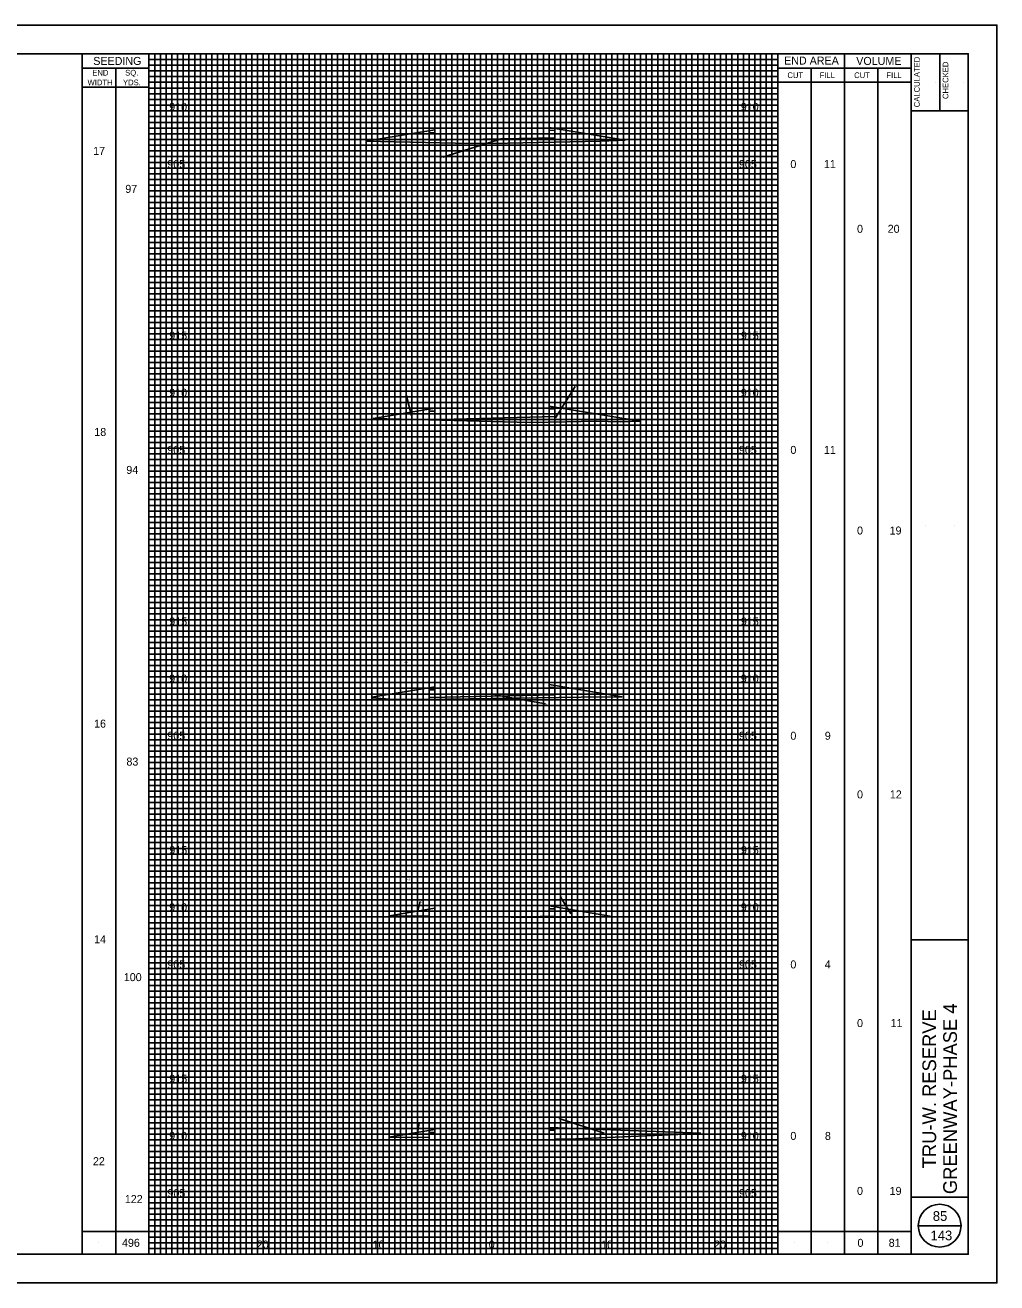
# Model space of a CAD drawing. Extents: x -73 to 160, y -2 to 1877.
# Drawn here: x 75 to 160, y 1262.5 to 1372.5 of the extents above; entities that cross this region are included whole.
import ezdxf

# ---------------------------------------------------------------- set-up
doc = ezdxf.new("R2010")
doc.units = 0
for name, color, linetype in [('DR_P_Flood_Boundary', 7, 'Continuous'), ('GK_Cells', 7, 'Continuous'), ('RD_X_Fence', 7, 'Continuous'), ('TX_X_5', 7, 'Continuous'), ('UT_P_Water_Cells', 7, 'Continuous'), ('XS_P_Pavt_Layers', 7, 'Continuous'), ('XS_P_Pavt_Surface', 7, 'Continuous'), ('XS_X_Ground_Line', 7, 'Continuous')]:
    doc.layers.add(name, color=color, linetype=linetype)

msp = doc.modelspace()

# ---------------------------------------------------------------- linework, layer by layer
at = {"layer": 'DR_P_Flood_Boundary'}
for p, q in [((90.83, 1265), (90.83, 1370)), ((95.83, 1265), (95.83, 1370)), ((100.83, 1265), (100.83, 1370)), ((105.83, 1265), (105.83, 1370)), ((110.83, 1265), (110.83, 1370)), ((115.83, 1265), (115.83, 1370)), ((120.83, 1265), (120.83, 1370)), ((125.83, 1265), (125.83, 1370)), ((130.83, 1265), (130.83, 1370)), ((135.83, 1265), (135.83, 1370)), ((85.83, 1365), (140.83, 1365)), ((85.83, 1360), (140.83, 1360)), ((85.83, 1355), (140.83, 1355)), ((85.83, 1350), (140.83, 1350)), ((85.83, 1345), (140.83, 1345)), ((85.83, 1340), (140.83, 1340)), ((85.83, 1335), (140.83, 1335)), ((85.83, 1330), (140.83, 1330)), ((85.83, 1325), (140.83, 1325)), ((85.83, 1320), (140.83, 1320)), ((85.83, 1315), (140.83, 1315)), ((85.83, 1310), (140.83, 1310)), ((85.83, 1305), (140.83, 1305)), ((85.83, 1300), (140.83, 1300)), ((85.83, 1295), (140.83, 1295)), ((85.83, 1290), (140.83, 1290)), ((85.83, 1285), (140.83, 1285)), ((85.83, 1280), (140.83, 1280)), ((85.83, 1275), (140.83, 1275)), ((85.83, 1270), (140.83, 1270))]:
    msp.add_line(p, q, dxfattribs=at)
at = {"layer": 'GK_Cells'}
for p, q in [((152.5, 1265), (152.5, 1370)), ((155, 1370), (155, 1365)), ((152.5, 1365), (157.5, 1365)), ((152.5, 1292.5), (157.5, 1292.5)), ((152.5, 1270), (157.5, 1270))]:
    msp.add_line(p, q, dxfattribs=at)
msp.add_lwpolyline([(0, 1370), (157.5, 1370), (157.5, 1265), (0, 1265)], close=True, dxfattribs=at)
at = {"layer": 'RD_X_Fence'}
for p, q in [((110.83, 1363.35), (104.77, 1362.34)), ((110.33, 1363.09), (110.83, 1363.1)), ((110.33, 1362.43), (110.33, 1363.09)), ((127.5, 1362.44), (120.83, 1363.55)), ((120.83, 1363.3), (121.33, 1363.31)), ((121.33, 1363.31), (121.33, 1362.65)), ((121.33, 1362.65), (110.33, 1362.43)), ((116.75, 1362.58), (111.55, 1360.94)), ((121.39, 1338.16), (123.11, 1340.91)), ((108.79, 1338.35), (108.35, 1340.06)), ((110.83, 1338.99), (105.45, 1338.09)), ((110.33, 1338.73), (110.83, 1338.74)), ((110.33, 1338.06), (110.33, 1338.73)), ((128.81, 1337.86), (120.83, 1339.19)), ((120.83, 1338.94), (121.33, 1338.95)), ((121.33, 1338.95), (121.33, 1338.28)), ((105.45, 1338.09), (110.33, 1337.97)), ((121.33, 1338.28), (110.33, 1337.97)), ((110.83, 1314.63), (105.32, 1313.71)), ((127.23, 1313.76), (120.83, 1314.83)), ((120.83, 1314.58), (121.33, 1314.59)), ((121.33, 1314.59), (121.33, 1313.92)), ((110.33, 1314.37), (110.83, 1314.38)), ((110.33, 1313.7), (110.33, 1314.37)), ((121.33, 1313.92), (110.33, 1313.7)), ((116.1, 1313.92), (120.53, 1313.15)), ((109.3, 1294.81), (109.56, 1295.85)), ((122.72, 1294.78), (121.87, 1296.2)), ((110.83, 1295.26), (106.86, 1294.6)), ((110.33, 1295), (110.83, 1295.01)), ((110.33, 1294.56), (110.33, 1295)), ((126.5, 1294.52), (120.83, 1295.46)), ((120.83, 1295.21), (121.33, 1295.22)), ((121.33, 1295.22), (121.33, 1294.56)), ((106.86, 1294.6), (110.33, 1294.56)), ((121.33, 1294.56), (117.5, 1294.48)), ((109.29, 1275.45), (109.46, 1276.48)), ((134.1, 1275.6), (120.83, 1276.1)), ((125.64, 1275.58), (121.72, 1276.88)), ((110.83, 1275.9), (106.82, 1275.23)), ((106.82, 1275.23), (110.33, 1275.22)), ((110.33, 1275.64), (110.83, 1275.65)), ((110.33, 1275.22), (110.33, 1275.64)), ((120.83, 1275.85), (121.33, 1275.86)), ((121.33, 1275.86), (121.33, 1275.2))]:
    msp.add_line(p, q, dxfattribs=at)
for points in [[(110.83, 1363.1), (110.83, 1363.25), (110.83, 1363.35)], [(120.83, 1363.55), (120.83, 1363.45), (120.83, 1363.3)], [(104.77, 1362.34), (112.64, 1362.18), (115.83, 1362.15), (125.37, 1362.34), (127.5, 1362.44)], [(110.83, 1338.74), (110.83, 1338.89), (110.83, 1338.99)], [(120.83, 1339.19), (120.83, 1339.09), (120.83, 1338.94)], [(110.33, 1337.97), (110.33, 1338.06)], [(110.33, 1337.97), (115.83, 1337.83), (119.16, 1337.75), (122.33, 1337.81), (124.95, 1337.86), (127.05, 1337.82), (128.81, 1337.86)], [(110.83, 1314.38), (110.83, 1314.52), (110.83, 1314.63)], [(120.83, 1314.83), (120.83, 1314.72), (120.83, 1314.58)], [(105.32, 1313.71), (105.33, 1313.68)], [(105.33, 1313.68), (107.3, 1313.51), (108.76, 1313.51), (109.33, 1313.52), (109.71, 1313.51), (115.83, 1313.6), (123.64, 1313.72), (127.23, 1313.76)], [(110.83, 1295.01), (110.83, 1295.16), (110.83, 1295.26)], [(120.83, 1295.46), (120.83, 1295.36), (120.83, 1295.21)], [(117.5, 1294.48), (120.77, 1294.44), (123.95, 1294.49), (126.5, 1294.52)], [(120.83, 1276.1), (120.83, 1276), (120.83, 1275.85)], [(110.83, 1275.65), (110.83, 1275.8), (110.83, 1275.9)], [(121.33, 1275.1), (122.46, 1275.08), (132.79, 1275.51), (134.1, 1275.6)], [(121.33, 1275.2), (121.33, 1275.1)]]:
    msp.add_lwpolyline(points, dxfattribs=at)
at = {"layer": 'TX_X_5'}
msp.add_lwpolyline([(-10, 1262.5), (160, 1262.5), (160, 1372.5), (-10, 1372.5)], close=True, dxfattribs=at)
at = {"layer": 'UT_P_Water_Cells'}
for p, q in [((85.83, 1369.5), (140.83, 1369.5)), ((86.33, 1265), (86.33, 1370)), ((86.83, 1265), (86.83, 1370)), ((87.33, 1265), (87.33, 1370)), ((87.83, 1265), (87.83, 1370)), ((88.33, 1265), (88.33, 1370)), ((88.83, 1265), (88.83, 1370)), ((89.33, 1265), (89.33, 1370)), ((89.83, 1265), (89.83, 1370)), ((90.33, 1265), (90.33, 1370)), ((91.33, 1265), (91.33, 1370)), ((91.83, 1265), (91.83, 1370)), ((92.33, 1265), (92.33, 1370)), ((92.83, 1265), (92.83, 1370)), ((93.33, 1265), (93.33, 1370)), ((93.83, 1265), (93.83, 1370)), ((94.33, 1265), (94.33, 1370)), ((94.83, 1265), (94.83, 1370)), ((95.33, 1265), (95.33, 1370)), ((96.33, 1265), (96.33, 1370)), ((96.83, 1265), (96.83, 1370)), ((97.33, 1265), (97.33, 1370)), ((97.83, 1265), (97.83, 1370)), ((98.33, 1265), (98.33, 1370)), ((98.83, 1265), (98.83, 1370)), ((99.33, 1265), (99.33, 1370)), ((99.83, 1265), (99.83, 1370)), ((100.33, 1265), (100.33, 1370)), ((101.33, 1265), (101.33, 1370)), ((101.83, 1265), (101.83, 1370)), ((102.33, 1265), (102.33, 1370)), ((102.83, 1265), (102.83, 1370)), ((103.33, 1265), (103.33, 1370)), ((103.83, 1265), (103.83, 1370)), ((104.33, 1265), (104.33, 1370)), ((104.83, 1265), (104.83, 1370)), ((105.33, 1265), (105.33, 1370)), ((106.33, 1265), (106.33, 1370)), ((106.83, 1265), (106.83, 1370)), ((107.33, 1265), (107.33, 1370)), ((107.83, 1265), (107.83, 1370)), ((108.33, 1265), (108.33, 1370)), ((108.83, 1265), (108.83, 1370)), ((109.33, 1265), (109.33, 1370)), ((109.83, 1265), (109.83, 1370)), ((110.33, 1265), (110.33, 1370)), ((111.33, 1265), (111.33, 1370)), ((111.83, 1265), (111.83, 1370)), ((112.33, 1265), (112.33, 1370)), ((112.83, 1265), (112.83, 1370)), ((113.33, 1265), (113.33, 1370)), ((113.83, 1265), (113.83, 1370)), ((114.33, 1265), (114.33, 1370)), ((114.83, 1265), (114.83, 1370)), ((115.33, 1265), (115.33, 1370)), ((116.33, 1265), (116.33, 1370)), ((116.83, 1265), (116.83, 1370)), ((117.33, 1265), (117.33, 1370)), ((117.83, 1265), (117.83, 1370)), ((118.33, 1265), (118.33, 1370)), ((118.83, 1265), (118.83, 1370)), ((119.33, 1265), (119.33, 1370)), ((119.83, 1265), (119.83, 1370)), ((120.33, 1265), (120.33, 1370)), ((121.33, 1265), (121.33, 1370)), ((121.83, 1265), (121.83, 1370)), ((122.33, 1265), (122.33, 1370)), ((122.83, 1265), (122.83, 1370)), ((123.33, 1265), (123.33, 1370)), ((123.83, 1265), (123.83, 1370)), ((124.33, 1265), (124.33, 1370)), ((124.83, 1265), (124.83, 1370)), ((125.33, 1265), (125.33, 1370)), ((126.33, 1265), (126.33, 1370)), ((126.83, 1265), (126.83, 1370)), ((127.33, 1265), (127.33, 1370)), ((127.83, 1265), (127.83, 1370)), ((128.33, 1265), (128.33, 1370)), ((128.83, 1265), (128.83, 1370)), ((129.33, 1265), (129.33, 1370)), ((129.83, 1265), (129.83, 1370)), ((130.33, 1265), (130.33, 1370)), ((131.33, 1265), (131.33, 1370)), ((131.83, 1265), (131.83, 1370)), ((132.33, 1265), (132.33, 1370)), ((132.83, 1265), (132.83, 1370)), ((133.33, 1265), (133.33, 1370)), ((133.83, 1265), (133.83, 1370)), ((134.33, 1265), (134.33, 1370)), ((134.83, 1265), (134.83, 1370)), ((135.33, 1265), (135.33, 1370)), ((136.33, 1265), (136.33, 1370)), ((136.83, 1265), (136.83, 1370)), ((137.33, 1265), (137.33, 1370)), ((137.83, 1265), (137.83, 1370)), ((138.33, 1265), (138.33, 1370)), ((138.83, 1265), (138.83, 1370)), ((139.33, 1265), (139.33, 1370)), ((139.83, 1265), (139.83, 1370)), ((140.33, 1265), (140.33, 1370)), ((85.83, 1369), (140.83, 1369)), ((85.83, 1368.5), (140.83, 1368.5)), ((85.83, 1368), (140.83, 1368)), ((85.83, 1367.5), (140.83, 1367.5)), ((85.83, 1367), (140.83, 1367)), ((85.83, 1366.5), (140.83, 1366.5)), ((85.83, 1366), (140.83, 1366)), ((85.83, 1365.5), (140.83, 1365.5)), ((85.83, 1364.5), (140.83, 1364.5)), ((85.83, 1364), (140.83, 1364)), ((85.83, 1363.5), (140.83, 1363.5)), ((85.83, 1363), (140.83, 1363)), ((85.83, 1362.5), (140.83, 1362.5)), ((85.83, 1362), (140.83, 1362)), ((85.83, 1361.5), (140.83, 1361.5)), ((85.83, 1361), (140.83, 1361)), ((85.83, 1360.5), (140.83, 1360.5)), ((85.83, 1359.5), (140.83, 1359.5)), ((85.83, 1359), (140.83, 1359)), ((85.83, 1358.5), (140.83, 1358.5)), ((85.83, 1358), (140.83, 1358)), ((85.83, 1357.5), (140.83, 1357.5)), ((85.83, 1357), (140.83, 1357)), ((85.83, 1356.5), (140.83, 1356.5)), ((85.83, 1356), (140.83, 1356)), ((85.83, 1355.5), (140.83, 1355.5)), ((85.83, 1354.5), (140.83, 1354.5)), ((85.83, 1354), (140.83, 1354)), ((85.83, 1353.5), (140.83, 1353.5)), ((85.83, 1353), (140.83, 1353)), ((85.83, 1352.5), (140.83, 1352.5)), ((85.83, 1352), (140.83, 1352)), ((85.83, 1351.5), (140.83, 1351.5)), ((85.83, 1351), (140.83, 1351)), ((85.83, 1350.5), (140.83, 1350.5)), ((85.83, 1349.5), (140.83, 1349.5)), ((85.83, 1349), (140.83, 1349)), ((85.83, 1348.5), (140.83, 1348.5)), ((85.83, 1348), (140.83, 1348)), ((85.83, 1347.5), (140.83, 1347.5)), ((85.83, 1347), (140.83, 1347)), ((85.83, 1346.5), (140.83, 1346.5)), ((85.83, 1346), (140.83, 1346)), ((85.83, 1345.5), (140.83, 1345.5)), ((85.83, 1344.5), (140.83, 1344.5)), ((85.83, 1344), (140.83, 1344)), ((85.83, 1343.5), (140.83, 1343.5)), ((85.83, 1343), (140.83, 1343)), ((85.83, 1342.5), (140.83, 1342.5)), ((85.83, 1342), (140.83, 1342)), ((85.83, 1341.5), (140.83, 1341.5)), ((85.83, 1341), (140.83, 1341)), ((85.83, 1340.5), (140.83, 1340.5)), ((85.83, 1339.5), (140.83, 1339.5)), ((85.83, 1339), (140.83, 1339)), ((85.83, 1338.5), (140.83, 1338.5)), ((85.83, 1338), (140.83, 1338)), ((85.83, 1337.5), (140.83, 1337.5)), ((85.83, 1337), (140.83, 1337)), ((85.83, 1336.5), (140.83, 1336.5)), ((85.83, 1336), (140.83, 1336)), ((85.83, 1335.5), (140.83, 1335.5)), ((85.83, 1334.5), (140.83, 1334.5)), ((85.83, 1334), (140.83, 1334)), ((85.83, 1333.5), (140.83, 1333.5)), ((85.83, 1333), (140.83, 1333)), ((85.83, 1332.5), (140.83, 1332.5)), ((85.83, 1332), (140.83, 1332)), ((85.83, 1331.5), (140.83, 1331.5)), ((85.83, 1331), (140.83, 1331)), ((85.83, 1330.5), (140.83, 1330.5)), ((85.83, 1329.5), (140.83, 1329.5)), ((85.83, 1329), (140.83, 1329)), ((85.83, 1328.5), (140.83, 1328.5)), ((85.83, 1328), (140.83, 1328)), ((85.83, 1327.5), (140.83, 1327.5)), ((85.83, 1327), (140.83, 1327)), ((85.83, 1326.5), (140.83, 1326.5)), ((85.83, 1326), (140.83, 1326)), ((85.83, 1325.5), (140.83, 1325.5)), ((85.83, 1324.5), (140.83, 1324.5)), ((85.83, 1324), (140.83, 1324)), ((85.83, 1323.5), (140.83, 1323.5)), ((85.83, 1323), (140.83, 1323)), ((85.83, 1322.5), (140.83, 1322.5)), ((85.83, 1322), (140.83, 1322)), ((85.83, 1321.5), (140.83, 1321.5)), ((85.83, 1321), (140.83, 1321)), ((85.83, 1320.5), (140.83, 1320.5)), ((85.83, 1319.5), (140.83, 1319.5)), ((85.83, 1319), (140.83, 1319)), ((85.83, 1318.5), (140.83, 1318.5)), ((85.83, 1318), (140.83, 1318)), ((85.83, 1317.5), (140.83, 1317.5)), ((85.83, 1317), (140.83, 1317)), ((85.83, 1316.5), (140.83, 1316.5)), ((85.83, 1316), (140.83, 1316)), ((85.83, 1315.5), (140.83, 1315.5)), ((85.83, 1314.5), (140.83, 1314.5)), ((85.83, 1314), (140.83, 1314)), ((85.83, 1313.5), (140.83, 1313.5)), ((85.83, 1313), (140.83, 1313)), ((85.83, 1312.5), (140.83, 1312.5)), ((85.83, 1312), (140.83, 1312)), ((85.83, 1311.5), (140.83, 1311.5)), ((85.83, 1311), (140.83, 1311)), ((85.83, 1310.5), (140.83, 1310.5)), ((85.83, 1309.5), (140.83, 1309.5)), ((85.83, 1309), (140.83, 1309)), ((85.83, 1308.5), (140.83, 1308.5)), ((85.83, 1308), (140.83, 1308)), ((85.83, 1307.5), (140.83, 1307.5)), ((85.83, 1307), (140.83, 1307)), ((85.83, 1306.5), (140.83, 1306.5)), ((85.83, 1306), (140.83, 1306)), ((85.83, 1305.5), (140.83, 1305.5)), ((85.83, 1304.5), (140.83, 1304.5)), ((85.83, 1304), (140.83, 1304)), ((85.83, 1303.5), (140.83, 1303.5)), ((85.83, 1303), (140.83, 1303)), ((85.83, 1302.5), (140.83, 1302.5)), ((85.83, 1302), (140.83, 1302)), ((85.83, 1301.5), (140.83, 1301.5)), ((85.83, 1301), (140.83, 1301)), ((85.83, 1300.5), (140.83, 1300.5)), ((85.83, 1299.5), (140.83, 1299.5)), ((85.83, 1299), (140.83, 1299)), ((85.83, 1298.5), (140.83, 1298.5)), ((85.83, 1298), (140.83, 1298)), ((85.83, 1297.5), (140.83, 1297.5)), ((85.83, 1297), (140.83, 1297)), ((85.83, 1296.5), (140.83, 1296.5)), ((85.83, 1296), (140.83, 1296)), ((85.83, 1295.5), (140.83, 1295.5)), ((85.83, 1294.5), (140.83, 1294.5)), ((85.83, 1294), (140.83, 1294)), ((85.83, 1293.5), (140.83, 1293.5)), ((85.83, 1293), (140.83, 1293)), ((85.83, 1292.5), (140.83, 1292.5)), ((85.83, 1292), (140.83, 1292)), ((85.83, 1291.5), (140.83, 1291.5)), ((85.83, 1291), (140.83, 1291)), ((85.83, 1290.5), (140.83, 1290.5)), ((85.83, 1289.5), (140.83, 1289.5)), ((85.83, 1289), (140.83, 1289)), ((85.83, 1288.5), (140.83, 1288.5)), ((85.83, 1288), (140.83, 1288)), ((85.83, 1287.5), (140.83, 1287.5)), ((85.83, 1287), (140.83, 1287)), ((85.83, 1286.5), (140.83, 1286.5)), ((85.83, 1286), (140.83, 1286)), ((85.83, 1285.5), (140.83, 1285.5)), ((85.83, 1284.5), (140.83, 1284.5)), ((85.83, 1284), (140.83, 1284)), ((85.83, 1283.5), (140.83, 1283.5)), ((85.83, 1283), (140.83, 1283)), ((85.83, 1282.5), (140.83, 1282.5)), ((85.83, 1282), (140.83, 1282)), ((85.83, 1281.5), (140.83, 1281.5)), ((85.83, 1281), (140.83, 1281)), ((85.83, 1280.5), (140.83, 1280.5)), ((85.83, 1279.5), (140.83, 1279.5)), ((85.83, 1279), (140.83, 1279)), ((85.83, 1278.5), (140.83, 1278.5)), ((85.83, 1278), (140.83, 1278)), ((85.83, 1277.5), (140.83, 1277.5)), ((85.83, 1277), (140.83, 1277)), ((85.83, 1276.5), (140.83, 1276.5)), ((85.83, 1276), (140.83, 1276)), ((85.83, 1275.5), (140.83, 1275.5)), ((85.83, 1274.5), (140.83, 1274.5)), ((85.83, 1274), (140.83, 1274)), ((85.83, 1273.5), (140.83, 1273.5)), ((85.83, 1273), (140.83, 1273)), ((85.83, 1272.5), (140.83, 1272.5)), ((85.83, 1272), (140.83, 1272)), ((85.83, 1271.5), (140.83, 1271.5)), ((85.83, 1271), (140.83, 1271)), ((85.83, 1270.5), (140.83, 1270.5)), ((85.83, 1269.5), (140.83, 1269.5)), ((85.83, 1269), (140.83, 1269)), ((85.83, 1268.5), (140.83, 1268.5)), ((85.83, 1268), (140.83, 1268)), ((85.83, 1267.5), (140.83, 1267.5)), ((85.83, 1267), (140.83, 1267)), ((85.83, 1266.5), (140.83, 1266.5)), ((85.83, 1266), (140.83, 1266)), ((85.83, 1265.5), (140.83, 1265.5))]:
    msp.add_line(p, q, dxfattribs=at)
at = {"layer": 'XS_X_Ground_Line'}
for p, q in [((80, 1265), (80, 1370)), ((85.83, 1265), (85.83, 1370)), ((140.83, 1265), (140.83, 1370)), ((146.67, 1265), (146.67, 1370)), ((85.83, 1368.75), (80, 1368.75)), ((82.92, 1265), (82.92, 1368.75)), ((140.83, 1368.75), (152.5, 1368.75)), ((143.75, 1265), (143.75, 1368.75)), ((149.58, 1265), (149.58, 1368.75)), ((140.83, 1367.5), (152.5, 1367.5)), ((154.6, 1367.52), (154.6, 1367.52)), ((157.1, 1367.52), (157.1, 1367.52)), ((85.83, 1367.08), (80, 1367.08)), ((153.75, 1328.75), (153.75, 1328.75)), ((156.26, 1328.75), (156.26, 1328.75)), ((155, 1281.46), (155, 1281.46)), ((153.12, 1267.5), (156.88, 1267.5)), ((155, 1267.92), (155, 1267.92)), ((80, 1267), (85.83, 1267)), ((140.83, 1267), (152.5, 1267)), ((155, 1266.22), (155, 1266.22)), ((81.46, 1266.03), (81.46, 1266.03)), ((84.37, 1266.03), (84.37, 1266.03)), ((142.29, 1266), (142.29, 1266)), ((145.21, 1266), (145.21, 1266)), ((148.12, 1266), (148.12, 1266)), ((151.04, 1266), (151.04, 1266))]:
    msp.add_line(p, q, dxfattribs=at)
msp.add_circle((155, 1267.5), 1.87, dxfattribs=at)

# ---------------------------------------------------------------- texts
at = {"layer": 'RD_X_Fence'}
for s, p in [('6.1', (108.25, 1365.46)), ('6.8', (116.36, 1365.77)), ('10.7', (111.37, 1360.87)), ('5.5', (107.42, 1343.39)), ('8.1', (115.44, 1342.9)), ('8.1', (122.99, 1340.84)), ('2.4', (108.21, 1339.99)), ('5.8', (108.17, 1316.7)), ('6.5', (115.11, 1316.7)), ('8.5', (120.38, 1313.08)), ('5.7', (117.18, 1297.87)), ('4.0', (108.42, 1297.71)), ('1.2', (109.45, 1295.78)), ('2.7', (121.73, 1296.13)), ('4.1', (108.75, 1278.89)), ('13.3', (118.98, 1279.15)), ('1.2', (109.34, 1276.41)), ('7.0', (121.57, 1276.81))]:
    msp.add_text(s, height=0.14, dxfattribs=at).set_placement(p)
at = {"layer": 'XS_P_Pavt_Layers'}
for s, p in [('85', (154.4, 1267.92)), ('143', (154.2, 1266.22))]:
    msp.add_text(s, height=0.85, dxfattribs=at).set_placement(p)
at = {"layer": 'XS_P_Pavt_Surface'}
for s, p in [('910', (87.6, 1365)), ('910', (137.6, 1365)), ('17', (80.95, 1361.15)), ('905', (87.44, 1360)), ('905', (137.44, 1360)), ('0', (141.94, 1360)), ('11', (144.87, 1360)), ('97', (83.76, 1357.83)), ('0', (147.77, 1354.34)), ('20', (150.45, 1354.34)), ('915', (87.61, 1345)), ('915', (137.61, 1345)), ('910', (87.6, 1340)), ('910', (137.6, 1340)), ('18', (81.05, 1336.57)), ('905', (87.44, 1335)), ('905', (137.44, 1335)), ('0', (141.94, 1335)), ('11', (144.87, 1335)), ('94', (83.85, 1333.25)), ('0', (147.77, 1327.95)), ('19', (150.62, 1327.95)), ('915', (87.61, 1320)), ('915', (137.61, 1320)), ('910', (87.6, 1315)), ('910', (137.6, 1315)), ('16', (81.03, 1311.06)), ('905', (87.44, 1310)), ('905', (137.44, 1310)), ('0', (141.94, 1310)), ('9', (144.95, 1310)), ('83', (83.86, 1307.74)), ('0', (147.77, 1304.87)), ('12', (150.64, 1304.87)), ('915', (87.61, 1300)), ('915', (137.61, 1300)), ('910', (87.6, 1295)), ('910', (137.6, 1295)), ('14', (81.03, 1292.2)), ('905', (87.44, 1290)), ('905', (137.44, 1290)), ('0', (141.94, 1290)), ('4', (144.94, 1290)), ('100', (83.63, 1288.89)), ('0', (147.77, 1284.87)), ('11', (150.7, 1284.87)), ('915', (87.61, 1280)), ('915', (137.61, 1280)), ('910', (87.6, 1275)), ('910', (137.6, 1275)), ('0', (141.94, 1275)), ('8', (144.96, 1275)), ('22', (80.93, 1272.79)), ('905', (87.45, 1270)), ('905', (137.45, 1270)), ('0', (147.77, 1270.19)), ('19', (150.62, 1270.19)), ('122', (83.72, 1269.48)), ('496', (83.47, 1265.65)), ('20', (95.26, 1265.5)), ('10', (105.39, 1265.5)), ('0', (115.55, 1265.5)), ('0', (115.55, 1265.5)), ('10', (125.39, 1265.5)), ('20', (135.26, 1265.5)), ('0', (147.81, 1265.65)), ('81', (150.54, 1265.65))]:
    msp.add_text(s, height=0.7, dxfattribs=at).set_placement(p)
for s, p in [('TRU-W. RESERVE', (154.69, 1272.52)), ('GREENWAY-PHASE 4', (156.51, 1270.26))]:
    msp.add_text(s, height=1.2, rotation=90, dxfattribs=at).set_placement(p)
at = {"layer": 'XS_X_Ground_Line'}
for s, height, p in [('SEEDING', 0.7, (80.96, 1369.02)), ('END AREA', 0.7, (141.39, 1369.05)), ('VOLUME', 0.7, (147.7, 1369.02)), ('END', 0.5, (80.87, 1368.09)), ('SQ.', 0.5, (83.75, 1368.09)), ('WIDTH', 0.5, (80.46, 1367.24)), ('YDS.', 0.5, (83.56, 1367.24)), ('CUT', 0.5, (141.68, 1367.87)), ('FILL', 0.5, (144.5, 1367.87)), ('CUT', 0.5, (147.52, 1367.87)), ('FILL', 0.5, (150.34, 1367.87)), ('143', 0.85, (154.2, 1266.22))]:
    msp.add_text(s, height=height, dxfattribs=at).set_placement(p)
for s, p in [('CALCULATED', (153.26, 1365.32)), ('CHECKED', (155.76, 1366.04))]:
    msp.add_text(s, height=0.5, rotation=90, dxfattribs=at).set_placement(p)

doc.saveas('drawing.dxf')
